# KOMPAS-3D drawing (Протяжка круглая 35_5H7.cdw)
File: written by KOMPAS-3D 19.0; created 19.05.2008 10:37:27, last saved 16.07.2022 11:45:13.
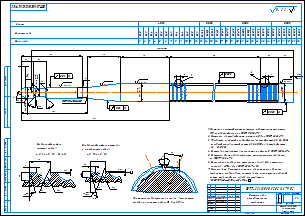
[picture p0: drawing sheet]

Sheet 1: A2, landscape

Document properties: Автор: 1; Организация: 1; Знак неуказанной шероховатости: 4; Параметр неуказанной шероховатости: Ra 3.2; Количество листов документа: 1; Полное имя файла: C:\ЮУрГУ\Режущий инструмент\Сделать\Для отправки\Протяжка круглая 35_5H7.cdw

Title block, sheet 1: Наименование: Протяжка для / цилиндрического / отверстия; designation: ФТТ-331.150305.2021.1679.02; scale: 1:1; organisation: Филиал ЮУрГУ (НИУ) / в г. Златоусте / Кафедра ТМСИ; Форматы листов документа: A2; Литера: у; stored path: C:\KUS\WINKUS\tms\Режущий инструмент\2008\Вариант 73\Протяжка моя круглая вар 73.cdw; Разработал: Цепилов Д.Ю.; Проверил: Дерябин И.П.

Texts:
  Линия-выноска #2
  Шероховатость
  Ra 3.2
  Ra 3.2 ( )
Dimensions and other numbers on the sheet: 1:1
